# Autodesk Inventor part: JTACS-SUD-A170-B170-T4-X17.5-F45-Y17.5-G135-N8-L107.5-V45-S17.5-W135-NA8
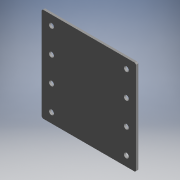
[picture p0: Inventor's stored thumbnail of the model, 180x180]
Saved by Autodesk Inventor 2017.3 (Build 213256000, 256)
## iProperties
Part Number: JTACS-SUD-A170-B170-T4-X17.5-F45-Y17.5-G135-N8-L107.5-V45-S17.5-W135-NA8
Material: Generic
Catalog Web Link: www.cadenas.de
Description: JTACS-Sheet Metal Mounting Plates/Brackets - Configurable - JTACS
Vendor: MISUMI
Document SubType Name: Modeling
Designer: partserver
Manufacturer: MISUMI
Mass: 113.532 g
Surface Area: 603.722 cm^2
Volume: 113.532 cm^3
Density: 1 g/cm^3
Appearance: PSOLRGB-175-175-175
Category: PARTsolutions
Company: MISUMI
Title: JTACS-SUD-A170-B170-T4-X17.5-F45-Y17.5-G135-N8-L107.5-V45-S17.5-W135-NA8
Author: Cadenas PARTsolutions
Comments: Sheet Metal Mounting Plates/Brackets - Configurable - JTACS
PSOL_IDENT_0: {$CADENAS_DATA\23d-libs\misumi\metric\25_machined_sheet_metals\jtacs.prj},371 {VTYP=3D},{NB=JTACS-SU
PSOL_IDENT_1: D-A170-B170-T4-X17.5-F45-Y17.5-G135-N8-L107.5-V45-S17.5-W135-NA8},{LINA=JTACS-SUD-A170-B170-T4-X17.5
PSOL_IDENT_2: -F45-Y17.5-G135-N8-L107.5-V45-S17.5-W135-NA8},{NN=JTACS},{DATE=04.06.2021 05:24:56},{GEOMDATE=14.12.
PSOL_IDENT_3: 2018 09:20:59},{VERSION=},{LINEID=10},{WBVAR=MS,A,B,T,ALT2,CC,X,F,YSE,Y,G,HS1,ND1,L,V,SSE,S,W,HS2,ND
PSOL_IDENT_4: 2},{WBNUMERIC=A,B,T,CC,X,F,Y,G,ND1,L,V,S,W,ND2}  {NB=JTACS-SUD-A170-B170-T4-X17.5-F45-Y17.5-G135-N8-
PSOL_IDENT_5: L107.5-V45-S17.5-W135-NA8},{LINA=JTACS-SUD-A170-B170-T4-X17.5-F45-Y17.5-G135-N8-L107.5-V45-S17.5-W13
PSOL_IDENT_6: 5-NA8},{KT=DUMMY},{PN=JTACS-SUD-A170-B170-T4-X17.5-F45-Y17.5-G135-N8-L107.5-V45-S17.5-W135-NA8},{TYP
PSOL_IDENT_7: E=JTACS},{MS=SUD},{MSALG= 'SP','SPB','SPU','SPK','AM','AMW','AMB','SUD' },{A=170},{AALG=[15:300/1]},
PSOL_IDENT_8: {B=170},{BALG=[15:300/1]},{T=4.0},{TALG= 1.0,'1.0',1.5,'1.5',2.0,'2.0',3.0,'3.0',4.0,'4.0',5.0,'5.0'
PSOL_IDENT_9: },{BB=2.0},{ALT2=},{ALT2ALG= '', 'w/o CC (Corner Cut Change)','CC','with CC (Corner Cut Change)'},{
PSOL_IDENT_10: ALT2PN=},{CC=0},{CCALG=[0]},{CCMIN=1},{CCMAX=10},{C3D=2},{X=17.5},{XALG=[0],[3.5:166.5/0.1]},{XMIN=3
PSOL_IDENT_11: .5},{XMIN1=3.5},{XMIN2=-77.9},{XMAX=166.5},{X3D=17.5},{F=45.0},{FALG=[0],[5:149/0.1]},{FMIN=5},{FMAX=
PSOL_IDENT_12: 149},{FMAX1=149},{FMAX2=230.5},{YSE=YSE},{YSEALG= '','Not Specified','YSE','Specified' },{Y=17.5},{Y
PSOL_IDENT_13: ALG=[3.5:166.5/0.1]},{YMIN=3.5},{YMIN1=3.5},{YMIN2=-10.4},{YMIN3=-100.400},{YMAX=166.5},{YMAX1=166.5
PSOL_IDENT_14: },{YMAX2=180.5},{YMAX3=270.500},{Y3D=17.5},{YPN=-Y17.5},{G=135.0},{GALG=[0],[5:149/0.1]},{GMIN=5},{G
PSOL_IDENT_15: MAX=149},{GMAX1=163},{GMAX2=253},{GMAX3=149.000},{HS1=N},{HS1ALG= 'N','N (Bolt Hole)','M','M (Tapped
PSOL_IDENT_16: Holes)' },{HS1PTN=1},{ND1=8},{ND1ALG=[3,4,5,6,8,10,12,14,16]},{ND1MAX=15.5},{ND1MAXVW=21.500},{ND1M
PSOL_IDENT_17: AX1=15.5},{ND1MAX2=21.5},{ND1MAX3=105.5},{ND1MAX4=15.5},{ND1MAX5=66.5},{ND1MAX6=15.5},{ND1MAX7=21.33
PSOL_IDENT_18: 4524},{ND1MAX8=84.974134},{ND1MAX9=21.334524},{ND1MAX10=84.974134},{ND13D=9},{ND13DALG=9.000},{DD=9.
PSOL_IDENT_19: 0},{ND1DD1=0},{BB1=2.000},{HH1=0.0},{L=107.5},{LALG=[0],[3.5:166.5/0.1]},{LALGLC1=0.000},{LALGLC2=0.
PSOL_IDENT_20: 000},{LMIN1=3.5},{LMIN11=3.5},{LMIN12=-77.9},{LMIN13=-77.9},{LMAX1=0},{LMAX1ALG=0.000},{LMAX11=0.000
PSOL_IDENT_21: },{LMAX12=0.000},{LMAX13=0.000},{LMAX14=0.000},{LMIN2=344},{LMIN2ALG=344.000},{LMIN21=344.000},{LMIN
PSOL_IDENT_22: 22=344.000},{LMIN23=344.000},{LMIN24=344.000},{LMAX2=0},{LMAX2ALG=0.000},{LMAX21=0.000},{LMAX22=0.00
PSOL_IDENT_23: 0},{LMAX23=0.000},{LMAX24=0.000},{LMIN3=344},{LMIN3ALG=344.000},{LMIN31=344},{LMIN32=344.000},{LMIN3
PSOL_IDENT_24: 3=344.000},{LMIN34=344.000},{LMAX3=166.5},{LMAX31=166.5},{LMAX32=248},{LMAX33=248},{LCALGA=4.950},{L
PSOL_IDENT_25: CALGB1=481.558},{LCALGB2=-8968.442},{LCALGB3=24414.673},{LCALGB4=32968.644},{LC1MAX=-254.318},{LC1MA
PSOL_IDENT_26: XALG=-254.318},{LC1MAX1=340.000},{LC1MAX2=-254.318},{LC1MIN=532.700},{LC1MINALG=532.657},{LC1MIN1=53
PSOL_IDENT_27: 2.657},{LC1MIN2=282.117},{LC2MAX=340.000},{LC2MAXALG=340.000},{LC2MAX1=340.000},{LC2MAX2=340.000},{L
PSOL_IDENT_28: C2MIN=0.000},{LC2MINALG=0.000},{LC2MIN1=0.000},{LC2MIN2=0.000},{L3D=107.5},{LBB1=11.5},{LBB2=16},{LB
PSOL_IDENT_29: B3=11.5},{LCBB1=17.678},{LCBB2=17.678},{LCBB3=81.317},{LCBB4=81.317},{LSEBB1=77},{LSEBB2=93},{LSEBB3=
PSOL_IDENT_30: 77},{LSEBB4=93},{V=45.0},{VALG=[0],[5:59/0.1]},{VPTN=3},{VMIN1=5},{VMAXS1=-100.400},{VMAXS2=270.500}
PSOL_IDENT_31: ,{VMAX1=0},{VMAX1ALG=0.000},{VMAX11=0.000},{VMAX12=0.000},{VMAX13=0.000},{VMAX14=0.000},{VMIN2=1000}
PSOL_IDENT_32: ,{VMIN2ALG=1000.000},{VMIN21=1000.000},{VMIN22=1000.000},{VMIN23=1000.000},{VMIN24=1000.000},{VMAX2=
PSOL_IDENT_33: 0},{VMAX2ALG=0.000},{VMAX21=0.000},{VMAX22=0.000},{VMAX23=0.000},{VMAX24=0.000},{VMIN3=1000},{VMIN3A
PSOL_IDENT_34: LG=1000.000},{VMIN31=1000.000},{VMIN32=1000.000},{VMIN33=1000.000},{VMIN34=1000.000},{VMAX3=59},{VMA
PSOL_IDENT_35: X31=344},{VMAX32=0},{VMAX33=0.000},{VMAX34=344.000},{VMAX35=344.000},{VMAX36=0.000},{VMAX37=0.000},{
PSOL_IDENT_36: VMAX38=344.000},{VMAX39=344.000},{VMAX310=0.000},{VMAX311=0.000},{VMAX312=344.000},{VMAX313=344.000}
PSOL_IDENT_37: ,{VMAX314=0.000},{VMAX315=0.000},{VMAX316=344.000},{VMAX317=140.500},{VMAX318=59.000},{VMAX319=140.5
PSOL_IDENT_38: 00},{VMAX320=140.500},{VCALGB1=37213.241},{VCALGB2=39233.430},{VCMAX=340.000},{VCMAXALG=340.000},{VC
PSOL_IDENT_39: MAX1=340.000},{VCMAX2=340.000},{VCMIN=0.000},{VCMINALG=0.000},{VCMIN1=0.000},{VCMIN2=0.000},{SSE=SSE
PSOL_IDENT_40: },{SSEALG= '','Not Specified','SSE','Specified' },{SSEPTN1=13.000},{SSEPTN2=63.000},{SSEPTN3=63.000}
PSOL_IDENT_41: ,{SSEPTN4=13.000},{SSEPTN5=13.000},{SSEPTN6=126.000},{SSEPTN7=-72.000},{SSEPTN8=-72.000},{SSEPTN9=12
PSOL_IDENT_42: 6.000},{SSEPTN10=13.000},{SSEPTNC=0.000},{SSEPTNC1=-100.500},{SSEPTNC2=-10.500},{S=17.5},{SALG=[3.5:
PSOL_IDENT_43: 166.5/0.1]},{SMIN1=3.500},{SMIN11=3.500},{SMIN12=-100.400},{SMIN13=-10.400},{SMAX1=344},{SMAX1ALG=34
PSOL_IDENT_44: 4.000},{SMAX11=344.000},{SMAX12=344.000},{SMAX13=344},{SMAX14=344},{SMIN2=0},{SMIN2ALG=0.000},{SMIN2
PSOL_IDENT_45: 1=0.000},{SMIN22=0.000},{SMIN23=0.000},{SMIN24=0.000},{SMAX2=344.000},{SMAX2ALG=344.000},{SMAX21=344
PSOL_IDENT_46: },{SMAX22=344.000},{SMAX23=344.000},{SMAX24=344.000},{SMIN3=0.000},{SMIN3ALG=0.000},{SMIN31=0.000},{
PSOL_IDENT_47: SMIN32=0.000},{SMIN33=0.000},{SMIN34=0.000},{SMAX3=166.500},{SMAX31=270.500},{SMAX32=180.500},{SMAX3
PSOL_IDENT_48: 3=166.500},{S3D=17.5},{SPN=-S17.5},{W=135.0},{WALG=[0],[5:149/0.1]},{WALG1=[0],[5:149/0.1]},{WPTN1=2
PSOL_IDENT_49: },{WMIN1=5.000},{WMAX1=344.000},{WMAX1ALG=344.000},{WMAX11=344.000},{WMAX12=344.000},{WMAX13=344.000
PSOL_IDENT_50: },{WMAX14=344.000},{WMIN2=5.000},{WMIN2ALG=5.000},{WMIN21=0.000},{WMIN22=0.000},{WMIN23=0.000},{WMIN
PSOL_IDENT_51: 24=0.000},{WMAX2=344.000},{WMAX2ALG=344.000},{WMAX21=344.000},{WMAX22=344.000},{WMAX23=344.000},{WMA
PSOL_IDENT_52: X24=344.000},{WMIN3=5.000},{WMIN3ALG=5.000},{WMIN31=0.000},{WMIN32=0.000},{WMIN33=0.000},{WMIN34=0.0
PSOL_IDENT_53: 00},{WMAX3=149.000},{WMAX31=208.000},{WMAX32=163.000},{WMAX33=149.000},{WALG2=[0],[5:163/0.1]},{WALG
PSOL_IDENT_54: 0=0},{WPTN2=2},{WMIN4=5},{WMAX4=344},{WMAX4ALG=344.000},{WMAX41=344.000},{WMAX42=344.000},{WMAX43=34
PSOL_IDENT_55: 4.000},{WMAX44=344.000},{WMAXY=344.000},{WMAXY1=344.000},{WMAXY2=344.000},{WMAXY3=344.000},{WMAXY4=3
PSOL_IDENT_56: 44.000},{WMAXW=344.000},{WMAXW1=344.000},{WMAXW2=344.000},{WMAXW3=344.000},{WMAXW4=344.000},{WMIN5=5
PSOL_IDENT_57: },{WMIN5ALG=5.000},{WMIN51=0.000},{WMIN52=0.000},{WMIN53=0.000},{WMIN54=0.000},{WMINY=0.000},{WMINY1=
PSOL_IDENT_58: 0.000},{WMINY2=0.000},{WMINY3=0.000},{WMINY4=0.000},{WMINW=0.000},{WMINW1=0.000},{WMINW2=nan},{WMINW
PSOL_IDENT_59: 3=0.000},{WMINW4=0.000},{WMAX5=344},{WMAX5ALG=344.000},{WMAX51=344.000},{WMAX52=344.000},{WMAX53=344
PSOL_IDENT_60: .000},{WMAX54=344.000},{WMIN6=5},{WMIN6ALG=5.000},{WMIN61=0.000},{WMIN62=0.000},{WMIN63=0.000},{WMIN
PSOL_IDENT_61: 64=0.000},{WMAX6=163},{WMAX61=371.1},{WMAX62=281.1},{WMAX63=461.1},{WMAX64=191.100},{WMAX65=163.000}
PSOL_IDENT_62: ,{WBB1=9.5},{WBB2=25.5},{WBB3=54.5},{WBB4=70.5},{HS2=NA},{HS2ALG= 'MA','MA (Tapped Holes)' ,'NA','NA
PSOL_IDENT_63: (Bolt Hole)','ZF','ZF (Counterbore Front)','ZB','ZB (Counterbore Back)' },{HS2PTN=1},{ND2=8},{ND2AL
PSOL_IDENT_64: G=[3,4,5,6,8,10,12,14,16]},{ND2MAX=15.5},{ND2MAXFG=21.500},{ND2MAXND1=38.500},{ND2MAX1=15.5},{ND2MAX
PSOL_IDENT_65: 2=66.5},{ND2MAX3=15.5},{ND2MAX4=105.5},{ND2MAX5=21.5},{ND2MAX6=15.5},{ND2MAX7=84.974134},{ND2MAX8=84
PSOL_IDENT_66: .974134},{ND2MAX9=21.334524},{ND2MAX10=21.334524},{ND2MAX11=83.5},{ND2MAX12=155.749807},{ND2MAX13=38
PSOL_IDENT_67: .5},{ND2MAX14=135.802495},{ND2MAX15=155.749807},{ND2MAX16=83.5},{ND2MAX17=135.802495},{ND2MAX18=38.5
PSOL_IDENT_68: },{ND2MAX19=128.5},{ND2MAX20=184.418831},{ND2MAX21=83.5},{ND2MAX22=155.749807},{ND2MAX23=184.418831}
PSOL_IDENT_69: ,{ND2MAX24=128.5},{ND2MAX25=155.749807},{ND2MAX26=83.5},{ND2BBALG=1.500},{ND2BBMAX=2.000},{ND23D=9},
PSOL_IDENT_70: {ND2DD1=0.0},{HH2=0.000},{XCIF=1},{LCIF=1}
NB: JTACS-SUD-A170-B170-T4-X17.5-F45-Y17.5-G135-N8-L107.5-V45-S17.5-W135-NA8
NN: JTACS
NT: Sheet Metal Mounting Plates/Brackets - Configurable - JTACS
NBSYN: $PN.
LINA: JTACS-SUD-A170-B170-T4-X17.5-F45-Y17.5-G135-N8-L107.5-V45-S17.5-W135-NA8
CATALOG: Misumi
PN: JTACS-SUD-A170-B170-T4-X17.5-F45-Y17.5-G135-N8-L107.5-V45-S17.5-W135-NA8
TYPE: JTACS
MS: SUD
A: 170
B: 170
T: 4.0
ALT2: w/o CC (Corner Cut Change)
CC: 0
X: 17.5
F: 45
YSE: Specified
Y: 17.5
G: 135
HS1: N (Bolt Hole)
ND1: 8
L: 107.5
V: 45
SSE: Specified
S: 17.5
W: 135
HS2: NA (Bolt Hole)
ND2: 8
SUPPLIER: MISUMI
ARTICLENO: JTACS-SUD-A170-B170-T4-X17.5-F45-Y17.5-G135-N8-L107.5-V45-S17.5-W135-NA8
BOMINFO: JTACS-SUD-A170-B170-T4-X17.5-F45-Y17.5-G135-N8-L107.5-V45-S17.5-W135-NA8
CREATOR: CADENAS GmbH
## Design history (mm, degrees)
sketch "_____1"
  geometry: L1 (-170, 168)-(-170, 2); L2 (-170, 2)-(-168, 0); L3 (-168, 0)-(-2, 0); L4 (-2, 0)-(0, 2); L5 (0, 2)-(0, 168); L6 (0, 168)-(-2, 170); L7 (-2, 170)-(-168, 170); L8 (-168, 170)-(-170, 168)
  constraints: 16 end point
extrude "Extrusion1" join sketch "_____1" distance "d0" = 4; taper "d1" = 0 deg
sketch "Sketch2"
  geometry: 1 further point
hole "Hole1" sketch "Sketch2" at (-17.5, 17.5) diameter "d2" = 9; stored, may be unused: countersink angle "d6" = 90 deg, drill point angle "d8" = 0 deg; dims "d3" = 6, "d4" = 4, "d5" = 2, "d7" = 4
sketch "Sketch3"
  geometry: 1 further point
hole "Hole2" sketch "Sketch3" at (-152.5, -17.5) diameter "d9" = 9; stored, may be unused: countersink angle "d13" = 90 deg, drill point angle "d15" = 0 deg; dims "d10" = 6, "d11" = 4, "d12" = 2, "d14" = 4
sketch "Sketch4"
  geometry: 1 further point
hole "Hole3" sketch "Sketch4" at (-17.5, 62.5) diameter "d16" = 9; stored, may be unused: countersink angle "d20" = 90 deg, drill point angle "d22" = 0 deg; dims "d17" = 6, "d18" = 4, "d19" = 2, "d21" = 4
sketch "Sketch5"
  geometry: 1 further point
hole "Hole4" sketch "Sketch5" at (-152.5, -62.5) diameter "d23" = 9; stored, may be unused: countersink angle "d27" = 90 deg, drill point angle "d29" = 0 deg; dims "d24" = 6, "d25" = 4, "d26" = 2, "d28" = 4
sketch "Sketch6"
  geometry: 1 further point
hole "Hole5" sketch "Sketch6" at (-17.5, 107.5) diameter "d30" = 9; stored, may be unused: countersink angle "d34" = 90 deg, drill point angle "d36" = 0 deg; dims "d31" = 6, "d32" = 4, "d33" = 2, "d35" = 4
sketch "Sketch7"
  geometry: 1 further point
hole "Hole6" sketch "Sketch7" at (-152.5, -107.5) diameter "d37" = 9; stored, may be unused: countersink angle "d41" = 90 deg, drill point angle "d43" = 0 deg; dims "d38" = 6, "d39" = 4, "d40" = 2, "d42" = 4
sketch "Sketch8"
  geometry: 1 further point
hole "Hole7" sketch "Sketch8" at (-17.5, -152.5) diameter "d44" = 9; stored, may be unused: countersink angle "d48" = 90 deg, drill point angle "d50" = 0 deg; dims "d45" = 6, "d46" = 4, "d47" = 2, "d49" = 4
sketch "Sketch9"
  geometry: 1 further point
hole "Hole8" sketch "Sketch9" at (-152.5, -152.5) diameter "d51" = 9; stored, may be unused: countersink angle "d55" = 90 deg, drill point angle "d57" = 0 deg; dims "d52" = 6, "d53" = 4, "d54" = 2, "d56" = 4
body "Solid1"
